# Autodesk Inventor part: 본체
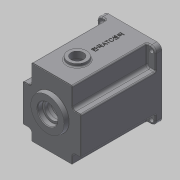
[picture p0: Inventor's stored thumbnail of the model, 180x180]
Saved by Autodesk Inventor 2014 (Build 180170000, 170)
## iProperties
Created: 2016-02
Part Number: 본체
Material: 일반
Document SubType Name: Modeling
Designer: mduedu
Density: 1 g/cm^3
Appearance: 기본값
Author: mduedu
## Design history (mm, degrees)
sketch "스케치1"
  geometry: L1 (-47, -47)-(47, -47); L2 (47, -47)-(47, 63); L3 (47, 63)-(-47, 63); L4 (-47, 63)-(-47, -47); 2 further points
  constraints: 8 end point, 2 parallel, 1 horizontal, 1 midpoint, 1 perpendicular, 1 vertical alignment
  dimensions: "d0" = 94 distance of L2.end L3.end; "d155" = 110 distance of L1.end L2.end; "d156" = 47 distance from line of L1 point (0, 0)
extrude "돌출1" new body sketch "스케치1" distance "d2" = 130; taper "d3" = 0 deg
sketch "스케치3"
  geometry: C1 r 40 at (0, 0); 1 further point
  constraints: 1 centre point, 1 coincident
  dimensions: "d9" = 80 diameter of C1
extrude "돌출3" cut sketch "스케치3" distance "d11" = 121; taper "d12" = 0 deg
sketch "스케치4"
  geometry: C1 r 21 at (0, 11); 1 further point
  constraints: 1 centre point, 1 vertical alignment
  dimensions: "d13" = 21 radius of C1; "d15" = 11 distance of point (0, 0) C1.centre
extrude "돌출4" join sketch "스케치4" distance "d16" = 7; taper "d17" = 0 deg
sketch "스케치5"
  geometry: C1 r 15 at (0, -20); 1 further point
  constraints: 1 centre point, 1 vertical alignment
  dimensions: "d18" = 15 radius of C1; "d20" = 20 distance of point (0, 0) C1.centre
extrude "돌출5" join sketch "스케치5" distance "d21" = 7; taper "d22" = 0 deg
sketch "스케치6"
  geometry: C1 r 28 at (0, 11); A1 r 21 centre (0, 11) between (8.978, -7.984) and (-8.978, -7.984) reference; 1 further point
  constraints: 1 centre point, 1 coincident
  dimensions: "d23" = 56 diameter of C1
extrude "돌출6" join sketch "스케치6" distance "d25" = 7; taper "d26" = -10 deg
hole "구멍1" diameter "d29" = 35; stored, may be unused: countersink angle "d33" = 90 deg, drill point angle "d35" = 0 deg; dims "d27" = 10, "d28" = 10, "d30" = 6, "d31" = 4, "d32" = 2, "d34" = 10
hole "구멍2" diameter "d38" = 22; stored, may be unused: countersink angle "d42" = 90 deg, drill point angle "d44" = 0 deg; dims "d36" = 10, "d37" = 10, "d39" = 6, "d40" = 4, "d41" = 2, "d43" = 7
hole "구멍3" diameter "d47" = 19; stored, may be unused: countersink angle "d51" = 90 deg, drill point angle "d53" = 0 deg; dims "d45" = 10, "d46" = 10, "d48" = 6, "d49" = 4, "d50" = 2, "d52" = 1
hole "구멍4" diameter "d56" = 32; stored, may be unused: countersink angle "d60" = 90 deg, drill point angle "d62" = 0 deg; dims "d54" = 10, "d55" = 10, "d57" = 6, "d58" = 4, "d59" = 2, "d61" = 8
hole "구멍5" diameter "d65" = 25; stored, may be unused: countersink angle "d69" = 90 deg, drill point angle "d71" = 0 deg; dims "d63" = 10, "d64" = 10, "d66" = 6, "d67" = 4, "d68" = 2, "d70" = 8
fillet "모깎기2" dims "d73" = 0.3
fillet "모깎기3" dims "d74" = 2
chamfer "모따기1" distance "d75" = 1; stored, may be unused: second distance "d76" = 2, angle "d77" = 45 deg
fillet "모깎기4" dims "d78" = 3
sketch "스케치16"
  geometry: L1 (-23, 32.726)-(23, 32.726); L2 (23, 32.726)-(23, 53); L3 (23, 53)-(-23, 53); L4 (-23, 53)-(-23, 32.726); L5 (-47, 63)-(47, 63) reference; 3 further points
  constraints: 8 end point, 2 parallel, 1 horizontal, 1 midpoint, 1 perpendicular, 1 vertical alignment, 2 other
  dimensions: "d160" = 46 distance of L2.end L3.end; "d163" = 10 distance between parallel lines of L3 L5
extrude "돌출15" cut sketch "스케치16" stored distance "d164" = 10; taper "d165" = 0 deg
fillet "모깎기5" dims "d79" = 2
fillet "모깎기15" dims "d166" = 5
sketch "스케치7"
  geometry: L1 (-23, 48)-(-23, 35.228) reference; L2 (23, 35.228)-(23, 48) reference; L3 (18, 53)-(-18, 53) reference; L4 (47, 63)-(47, -47) reference; L5 (47, -47)-(-47, -47) reference; L6 (-47, -47)-(-47, 63) reference; L7 (-47, 63)-(47, 63) reference; L8 (-26, 48)-(-26, 35.228); L9 (26, 35.228)-(26, 48); L10 (18, 56)-(-18, 56); C1 r 43 at (0, 0); A1 r 5 centre (-18, 48) between (-18, 53) and (-23, 48) reference; A2 r 5 centre (-28, 35.228) between (-24.889, 31.314) and (-23, 35.228) reference; A3 r 40 centre (0, 0) between (-24.889, 31.314) and (24.889, 31.314) reference; A4 r 5 centre (28, 35.228) between (23, 35.228) and (24.889, 31.314) reference; A5 r 5 centre (18, 48) between (23, 48) and (18, 53) reference; A6 r 8 centre (-18, 48) between (-18, 56) and (-26, 48); A7 r 2 centre (-28, 35.228) between (-26.756, 33.662) and (-26, 35.228); A8 r 43 centre (0, 0) between (-26.756, 33.662) and (26.756, 33.662); A9 r 2 centre (28, 35.228) between (26, 35.228) and (26.756, 33.662); A10 r 8 centre (18, 48) between (26, 48) and (18, 56); 1 further point
  constraints: 10 point on circle, 6 centre point, 6 end point, 1 coincident, 7 other
  dimensions: "d80" = 86 diameter of C1; "d167" = 3 distance between parallel lines of L3 L10
extrude "돌출7" cut sketch "스케치7" distance "d83" = 9; taper "d84" = 0 deg
sketch "스케치8" dims "d168" = 36
  geometry: L1 (-36, 4)-(-39.799, 4); L2 (-36, -4)-(-39.799, -4); A1 r 4 centre (-36, 0) between (-36, 4) and (-36, -4); A2 r 40 centre (0, 0) between (-24.889, 31.314) and (24.889, 31.314) reference; A3 r 40 centre (0, 0) between (-39.799, 4) and (-39.799, -4); 2 further points
  constraints: 5 point on circle, 4 end point, 2 centre point, 2 coincident, 2 horizontal alignment, 2 tangent, 1 horizontal, 1 parallel, 2 other
  dimensions: "d169" = 4 radius of A1
extrude "돌출9" join sketch "스케치8" stored distance "d89" = 9; taper "d90" = 0 deg
fillet "모깎기6" dims "d91" = 3.5
sketch "스케치9"
  geometry: L1 (47, 63)-(-47, 63) reference; L2 (47, -47)-(47, 63) reference; L3 (47, 63)-(33, 63); L4 (33, 63)-(33, 30); L5 (33, 30)-(47, 30); L6 (47, 30)-(47, 63); 2 further points
  constraints: 8 end point, 2 parallel, 1 horizontal, 1 perpendicular
  dimensions: "d95" = 33 distance from line of L4 point (0, 0); "d96" = 30 distance from line of L5 point (0, 0)
extrude "돌출10" cut sketch "스케치9" distance "d97" = 120; taper "d98" = 0 deg
sketch "스케치11"
  geometry: L1 (-40, -40)-(40, -40); L2 (40, -40)-(40, 56); L3 (40, 56)-(-40, 56); L4 (-40, 56)-(-40, -40); L5 (-47, -47)-(47, -47) reference; L6 (47, 63)-(-47, 63) reference; L7 (-47, 63)-(-47, -47) reference; C1 r 3.5 at (-40, 56); C2 r 3.5 at (40, 56); C3 r 3.5 at (40, -40); C4 r 3.5 at (-40, -40); 1 further point
  constraints: 8 end point, 4 centre point, 4 coincident, 3 equal radius, 2 parallel, 1 horizontal, 1 perpendicular
  dimensions: "d109" = 80 distance of L2.end L3.end; "d112" = 7 diameter of C1; "d157" = 7 distance from line of L1.start L5; "d158" = 7 distance between parallel lines of L6 L3; "d159" = 7 distance from line of L7 L3.end
extrude "돌출12" cut sketch "스케치11" stored distance "d113" = 63; taper "d114" = 0 deg
fillet "모깎기7" dims "d115" = 8
fillet "모깎기8" dims "d116" = 5
fillet "모깎기11" dims "d119" = 2
fillet "모깎기12" dims "d120" = 2
fillet "모깎기13" dims "d121" = 2
sketch "스케치12"
  geometry: 3 further points
  constraints: 2 horizontal alignment
hole "구멍6" sketch "스케치12" at (36, 0), (-36, 0) diameter "d122" = 3.242; stored, may be unused: countersink angle "d126" = 90 deg, drill point angle "d128" = 120 deg; dims "d123" = 7, "d124" = 4, "d125" = 2, "d127" = 9
sketch "스케치13"
  geometry: L1 (-33, 35)-(-33, 61) reference; L2 (-31, 63)-(31, 63) reference; L3 (33, 61)-(33, 35) reference; L4 (33, -35)-(33, -45) reference; L5 (31, -47)-(-31, -47) reference; L6 (-33, -45)-(-33, -35) reference; L7 (38, 30)-(45, 30) reference; L8 (47, 28)-(47, -28) reference; L9 (45, -30)-(38, -30) reference; L10 (-38, -30)-(-45, -30) reference; L11 (-47, -28)-(-47, 28) reference; L12 (-45, 30)-(-38, 30) reference; L13 (31, 62)-(-31, 62); L14 (-32, 61)-(-32, 35); L15 (-38, 29)-(-45, 29); L16 (-46, 28)-(-46, -28); L17 (-45, -29)-(-38, -29); L18 (-32, -35)-(-32, -45); L19 (-31, -46)-(31, -46); L20 (32, -45)-(32, -35); L21 (38, -29)-(45, -29); L22 (46, -28)-(46, 28); L23 (45, 29)-(38, 29); L24 (32, 35)-(32, 61); L25 (38, 30)-(45, 30) reference; L26 (47, 28)-(47, -28) reference; L27 (45, -30)-(38, -30) reference; L28 (33, -35)-(33, -45) reference; L29 (31, -47)-(-31, -47) reference; L30 (-33, -45)-(-33, -35) reference; L31 (-38, -30)-(-45, -30) reference; L32 (-47, -28)-(-47, 28) reference; L33 (-45, 30)-(-38, 30) reference; L34 (-33, 35)-(-33, 61) reference; L35 (33, 61)-(33, 35) reference; L36 (-31, 63)-(31, 63) reference; C1 r 16 at (0, 11) reference; C2 r 28 at (0, 11) reference; C3 r 16 at (0, 11) reference; C4 r 28 at (0, 11) reference; A1 r 5 centre (-38, 35) between (-38, 30) and (-33, 35) reference; A2 r 2 centre (-31, 61) between (-31, 63) and (-33, 61) reference; A3 r 2 centre (31, 61) between (33, 61) and (31, 63) reference; A4 r 5 centre (38, 35) between (33, 35) and (38, 30) reference; A5 r 5 centre (38, -35) between (38, -30) and (33, -35) reference; A6 r 2 centre (31, -45) between (31, -47) and (33, -45) reference; A7 r 2 centre (-31, -45) between (-33, -45) and (-31, -47) reference; A8 r 5 centre (-38, -35) between (-33, -35) and (-38, -30) reference; A9 r 2 centre (45, 28) between (47, 28) and (45, 30) reference; A10 r 2 centre (45, -28) between (45, -30) and (47, -28) reference; A11 r 2 centre (-45, -28) between (-47, -28) and (-45, -30) reference; A12 r 2 centre (-45, 28) between (-45, 30) and (-47, 28) reference; A13 r 1 centre (-31, 61) between (-31, 62) and (-32, 61); A14 r 6 centre (-38, 35) between (-38, 29) and (-32, 35); A15 r 1 centre (-45, 28) between (-45, 29) and (-46, 28); A16 r 1 centre (-45, -28) between (-46, -28) and (-45, -29); A17 r 6 centre (-38, -35) between (-32, -35) and (-38, -29); A18 r 1 centre (-31, -45) between (-32, -45) and (-31, -46); A19 r 1 centre (31, -45) between (31, -46) and (32, -45); A20 r 6 centre (38, -35) between (38, -29) and (32, -35); A21 r 1 centre (45, -28) between (45, -29) and (46, -28); A22 r 1 centre (45, 28) between (46, 28) and (45, 29); A23 r 6 centre (38, 35) between (32, 35) and (38, 29); A24 r 1 centre (31, 61) between (32, 61) and (31, 62); A25 r 5 centre (38, 35) between (33, 35) and (38, 30) reference; A26 r 2 centre (45, 28) between (47, 28) and (45, 30) reference; A27 r 2 centre (45, -28) between (45, -30) and (47, -28) reference; A28 r 5 centre (38, -35) between (38, -30) and (33, -35) reference; A29 r 2 centre (31, -45) between (31, -47) and (33, -45) reference; A30 r 2 centre (-31, -45) between (-33, -45) and (-31, -47) reference; A31 r 5 centre (-38, -35) between (-33, -35) and (-38, -30) reference; A32 r 2 centre (-45, -28) between (-47, -28) and (-45, -30) reference; A33 r 2 centre (-45, 28) between (-45, 30) and (-47, 28) reference; A34 r 5 centre (-38, 35) between (-38, 30) and (-33, 35) reference; A35 r 2 centre (-31, 61) between (-31, 63) and (-33, 61) reference; A36 r 2 centre (31, 61) between (33, 61) and (31, 63) reference
  constraints: 24 end point, 24 point on circle, 12 centre point, 23 other
  dimensions: "d154" = 1 distance between parallel lines of L13 L2
extrude "돌출13" cut sketch "스케치13" distance "d130" = 1; taper "d131" = 0 deg
fillet "모깎기14" dims "d147" = 0.3
sketch "스케치15"
  geometry: L1 (78, 0)-(0, 0) reference; 3 further points
  constraints: 1 midpoint, 1 vertical alignment, 1 other
  dimensions: "d148" = 40 distance of point (39, -40) point (39, 0)
feature "엠보싱1" sketch "스케치15" dims "d22" = 0, "d149" = 0.5, "d150" = 0
chamfer "모따기4" distance "d151" = 1; stored, may be unused: second distance "d152" = 2, angle "d153" = 45 deg
sketch "스케치17"
  geometry: L1 (39.004, -17.213)-(39.004, -18.809) reference; L2 (39.004, -18.809)-(38.548, -18.809) reference; L3 (38.548, -18.809)-(38.548, -17.213) reference; L4 (38.548, -17.213)-(35.455, -17.213) reference; L5 (35.455, -17.213)-(35.455, -16.822) reference; L6 (35.772, -16.659)-(42.578, -16.659) reference; L7 (42.578, -16.659)-(42.578, -17.213) reference; L8 (42.578, -17.213)-(39.004, -17.213) reference; L9 (38.223, -56.73)-(38.695, -56.73) reference; L10 (38.695, -56.73)-(38.695, -58.073) reference; L11 (38.695, -58.073)-(40.787, -58.073) reference; L12 (40.787, -58.073)-(40.787, -58.643) reference; L13 (40.787, -58.643)-(35.398, -58.643) reference; L14 (35.398, -58.643)-(35.398, -58.277) reference; L15 (35.715, -58.073)-(38.223, -58.073) reference; L16 (38.223, -58.073)-(38.223, -56.73) reference; L17 (41.927, -57.813)-(42.383, -57.813) reference; L18 (42.383, -57.813)-(42.383, -63.031) reference; L19 (42.383, -63.031)-(40.429, -63.031) reference; L20 (40.429, -63.031)-(40.429, -62.608) reference; L21 (40.689, -62.478)-(41.927, -62.478) reference; L22 (41.927, -62.478)-(41.927, -57.813) reference; L23 (36.09, -60.849)-(36.09, -62.624) reference; L24 (36.09, -62.624)-(35.666, -62.624) reference; L25 (35.666, -62.624)-(35.666, -60.849) reference; L26 (35.666, -60.849)-(36.09, -60.849) reference; L27 (37.058, -64.057)-(36.635, -64.057) reference; L28 (36.635, -64.057)-(36.635, -59.539) reference; L29 (36.635, -59.539)-(37.058, -59.539) reference; L30 (37.058, -59.539)-(37.058, -64.057) reference; L31 (42.138, -43.501)-(40.307, -44.168) reference; L32 (40.307, -44.168)-(40.307, -46.871) reference; L33 (40.307, -46.871)-(42.138, -47.555) reference; L34 (42.138, -47.555)-(42.138, -48.133) reference; L35 (42.138, -48.133)-(36.138, -45.853) reference; L36 (36.138, -45.853)-(36.138, -45.202) reference; L37 (36.138, -45.202)-(42.138, -42.923) reference; L38 (42.138, -42.923)-(42.138, -43.501) reference; L39 (36.725, -45.536)-(39.81, -46.684) reference; L40 (39.81, -46.684)-(39.81, -44.364) reference; L41 (39.81, -44.364)-(36.725, -45.536) reference; L42 (40.022, -52.114)-(40.022, -49.94) reference; L43 (40.022, -49.94)-(42.57, -49.94) reference; L44 (42.57, -49.94)-(42.57, -50.494) reference; L45 (42.57, -50.494)-(40.469, -50.494) reference; L46 (40.469, -50.494)-(40.469, -55.094) reference; L47 (40.469, -55.094)-(40.022, -55.094) reference; L48 (40.022, -55.094)-(40.022, -52.659) reference; L49 (40.022, -52.659)-(38.556, -52.659) reference; L50 (38.556, -52.659)-(38.556, -55.973) reference; L51 (38.556, -55.973)-(38.109, -55.973) reference; L52 (38.109, -55.973)-(38.109, -50.73) reference; L53 (36.106, -50.388)-(36.106, -54.955) reference; L54 (36.106, -54.955)-(35.65, -54.955) reference; L55 (35.65, -54.955)-(35.65, -49.81) reference; L56 (38.109, -50.136)-(38.109, -48.768) reference; L57 (38.109, -48.768)-(38.556, -48.768) reference; L58 (38.556, -48.768)-(38.556, -52.114) reference; L59 (38.556, -52.114)-(40.022, -52.114) reference; L60 (36.138, -38.168)-(36.635, -38.168) reference; L61 (36.635, -38.168)-(36.635, -40.041) reference; L62 (36.635, -40.041)-(42.138, -40.041) reference; L63 (42.138, -40.041)-(42.138, -40.586) reference; L64 (42.138, -40.586)-(36.635, -40.586) reference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; C1 r 10 at (39, -89); A1 r 4 centre (4, -12) between (8, -12) and (4, -8) reference; A2 r 4 centre (74, -12) between (74, -8) and (70, -12) reference; 61 further points
  constraints: 2 end point, 1 centre point, 1 midpoint, 1 point on line, 76 other
  dimensions: "d170" = 20 diameter of C1; "d171" = 41 distance from line of C1.centre L110
extrude "돌출16" cut sketch "스케치17" stored distance "d172" = 10; taper "d173" = 0 deg
sketch "스케치18"
  geometry: C1 r 10 at (39, -89) reference; C2 r 15 at (39, -89); 1 further point
  constraints: 1 centre point, 1 coincident
  dimensions: "d174" = 30 diameter of C2
extrude "돌출17" join sketch "스케치18" distance "d175" = 5; taper "d176" = 0 deg
fillet "모깎기16" dims "d177" = 2
sketch "스케치19"
  geometry: C1 r 10 at (18, 80) reference; C2 r 15 at (18, 80); 1 further point
  constraints: 1 centre point, 1 coincident
  dimensions: "d178" = 30 diameter of C2
extrude "돌출18" cut sketch "스케치19" distance "d181" = 5; taper "d182" = 0 deg
chamfer "모따기5" distance "d183" = 0.5; stored, may be unused: second distance "d184" = 2, angle "d185" = 45 deg
node "솔리드1"
pattern_circular "원형 패턴1" dims angle "d93" = 360 deg
mirror "대칭1"
mirror "대칭2"
node "절단 모서리 투영1"
node "절단 모서리 투영2"
node "절단 모서리 투영3"
node "절단 모서리 투영4"
